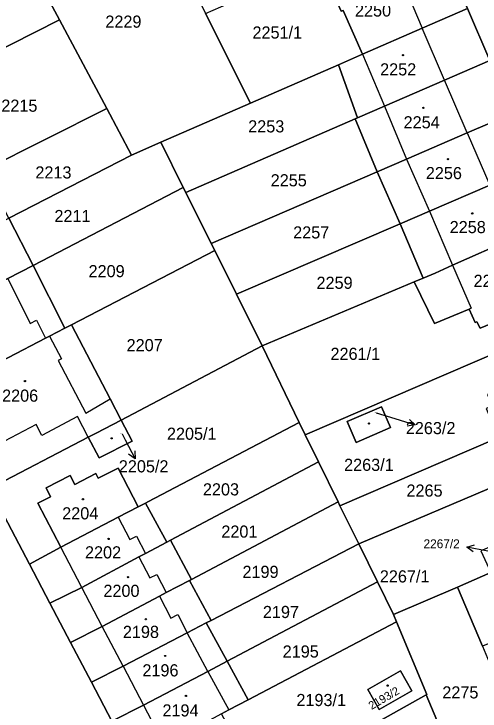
# Model space of a CAD drawing. Extents: x -596233 to -595156, y -1161235 to -1159375.
# Drawn here: x -595917.1 to -595851.8, y -1160689.1 to -1160591.4 of the extents above; entities that cross this region are included whole.
import ezdxf

# ---------------------------------------------------------------- set-up
doc = ezdxf.new("R2010")
doc.units = 0
for name, color, linetype in [('KN_CAR_KR', 7, 'Continuous'), ('KN_KULTURY', 7, 'Continuous'), ('KN_PARC_CIS_POM', 7, 'Continuous'), ('KN_PARC_CIS_POZ', 7, 'Continuous'), ('KN_PARC_CIS_STAV', 7, 'Continuous'), ('KN_PARC_PLOCHA', 7, 'Continuous'), ('PARC_C_SIPKA', 7, 'Continuous'), ('parcely_l', 7, 'Continuous')]:
    doc.layers.add(name, color=color, linetype=linetype)

msp = doc.modelspace()

# ---------------------------------------------------------------- linework, layer by layer
at = {"layer": 'KN_CAR_KR'}
for points in [[(-595863.31, -1160585.25), (-595859.91, -1160593.35)], [(-595856.78, -1160600.64), (-595859.91, -1160593.35)], [(-595868.26, -1160597), (-595865.21, -1160604.3)], [(-595853.61, -1160608.04), (-595856.78, -1160600.64)], [(-595865.21, -1160604.3), (-595862.1, -1160611.7)], [(-595853.61, -1160608.04), (-595850.46, -1160615.35)], [(-595862.1, -1160611.7), (-595858.89, -1160618.98)], [(-595858.89, -1160618.98), (-595855.67, -1160626.59)], [(-595855.67, -1160626.59), (-595853.07, -1160632.61)], [(-595917.95, -1160628.46), (-595914.82, -1160634.73)], [(-595853.07, -1160632.61), (-595853.34, -1160632.73)], [(-595914.82, -1160634.73), (-595913.93, -1160634.28)], [(-595913.93, -1160634.28), (-595912.67, -1160636.81)], [(-595912.11, -1160636.52), (-595910.45, -1160639.69)], [(-595910.45, -1160639.69), (-595910.92, -1160639.93)], [(-595910.92, -1160639.93), (-595907.05, -1160647.33)], [(-595907.05, -1160647.33), (-595903.64, -1160645.3)], [(-595908.21, -1160647.78), (-595913.17, -1160650.47)], [(-595906.69, -1160650.69), (-595908.21, -1160647.78)], [(-595913.99, -1160648.92), (-595918.41, -1160651.25)], [(-595913.17, -1160650.47), (-595913.99, -1160648.92)], [(-595902.5, -1160661.91), (-595900.86, -1160665.05)], [(-595900.86, -1160665.05), (-595899.93, -1160664.56)], [(-595899.93, -1160664.56), (-595898.66, -1160666.99)], [(-595907.6, -1160671.74), (-595910.53, -1160666.12)], [(-595899.59, -1160667.48), (-595898.05, -1160670.42)], [(-595898.05, -1160670.42), (-595897.09, -1160669.92)], [(-595897.09, -1160669.92), (-595895.76, -1160672.48)], [(-595904.73, -1160677.22), (-595907.6, -1160671.74)], [(-595896.71, -1160672.98), (-595895.13, -1160676.06)], [(-595895.13, -1160676.06), (-595894.13, -1160675.54)], [(-595894.13, -1160675.54), (-595892.81, -1160678.11)], [(-595901.82, -1160682.79), (-595904.73, -1160677.22)], [(-595889.96, -1160683.52), (-595892.81, -1160678.11)], [(-595901.82, -1160682.79), (-595898.96, -1160688.27)], [(-595889.96, -1160683.52), (-595887, -1160688.9)], [(-595898.96, -1160688.27), (-595896.07, -1160693.8)]]:
    msp.add_lwpolyline(points, dxfattribs=at)
at = {"layer": 'KN_KULTURY'}
for centre, radius in [((-595862.6, -1160597.13), 0.09), ((-595862.6, -1160597.13), 0.0398), ((-595859.75, -1160604.52), 0.09), ((-595859.75, -1160604.52), 0.0398), ((-595856.29, -1160611.71), 0.09), ((-595856.29, -1160611.71), 0.0398), ((-595852.9, -1160619.31), 0.09), ((-595852.9, -1160619.31), 0.0398), ((-595915.56, -1160642.82), 0.09), ((-595915.56, -1160642.82), 0.0398), ((-595867.35, -1160648.77), 0.09), ((-595867.35, -1160648.77), 0.0398), ((-595903.41, -1160650.85), 0.09), ((-595903.41, -1160650.85), 0.0398), ((-595907.43, -1160659.39), 0.09), ((-595907.43, -1160659.39), 0.0398), ((-595903.84, -1160664.95), 0.09), ((-595903.84, -1160664.95), 0.0398), ((-595901.13, -1160670.31), 0.09), ((-595901.13, -1160670.31), 0.0398), ((-595898.62, -1160676.21), 0.09), ((-595898.62, -1160676.21), 0.0398), ((-595895.91, -1160681.36), 0.09), ((-595895.91, -1160681.36), 0.0398), ((-595864.75, -1160685.51), 0.09), ((-595864.75, -1160685.51), 0.0398), ((-595893.01, -1160686.96), 0.09), ((-595893.01, -1160686.96), 0.0398)]:
    msp.add_circle(centre, radius, dxfattribs=at)
at = {"layer": 'KN_PARC_PLOCHA'}
for points in [[(-595850.43, -1160597.88), (-595853.57, -1160590.58), (-595859.06, -1160577.63), (-595864.83, -1160564.04), (-595868.29, -1160555.87), (-595870.71, -1160550.16), (-595874.62, -1160540.96), (-595876.97, -1160535.43), (-595882.36, -1160522.78), (-595882.91, -1160521.4), (-595885.64, -1160515.05), (-595887.02, -1160513.99), (-595888.53, -1160513.75), (-595890, -1160514.14), (-595887.17, -1160511.46), (-595869.41, -1160494.3), (-595869.87, -1160496.82), (-595869.71, -1160496.86), (-595864.99, -1160508.05), (-595863.86, -1160510.74), (-595864.05, -1160510.83), (-595853.97, -1160534.74), (-595853.68, -1160534.62), (-595849.94, -1160543.33)], [(-595955.55, -1160590.59), (-595949.46, -1160602.27), (-595945.4, -1160610.08), (-595938.93, -1160622.5), (-595935.44, -1160629.19), (-595932, -1160635.8), (-595927.43, -1160644.58), (-595920.5, -1160657.89), (-595914.93, -1160668.51), (-595912.07, -1160673.95), (-595909.16, -1160679.49), (-595906.25, -1160685.05), (-595903.39, -1160690.49)]]:
    msp.add_lwpolyline(points, dxfattribs=at)
for points in [[(-595907.77, -1160568.43), (-595898.29, -1160588.13), (-595892.95, -1160585.89), (-595890.25, -1160591.3), (-595883.98, -1160603.87), (-595896.51, -1160609.35), (-595900.63, -1160611.15), (-595904.1, -1160604.62), (-595910.73, -1160592.17), (-595914.88, -1160584.4), (-595916.4, -1160581.55), (-595909.61, -1160574.84), (-595910.51, -1160573.17), (-595910.44, -1160572.58), (-595910.47, -1160569.9), (-595912.95, -1160567.08), (-595910.04, -1160564.23), (-595909.12, -1160565.15)], [(-595853.57, -1160590.58), (-595859.91, -1160593.35), (-595868.26, -1160597), (-595870.96, -1160590.85), (-595871.24, -1160590.97), (-595872.13, -1160588.95), (-595871.85, -1160588.83), (-595872.24, -1160587.95), (-595873.19, -1160585.72), (-595869.74, -1160584.25), (-595868.71, -1160586.43), (-595868.32, -1160587.36), (-595863.31, -1160585.25), (-595864.76, -1160582.09), (-595869.74, -1160584.25), (-595870.47, -1160582.6), (-595859.06, -1160577.63)], [(-595869.74, -1160584.25), (-595873.19, -1160585.72), (-595872.24, -1160587.95), (-595871.85, -1160588.83), (-595872.13, -1160588.95), (-595871.24, -1160590.97), (-595870.96, -1160590.85), (-595868.26, -1160597), (-595871.65, -1160598.48), (-595883.98, -1160603.87), (-595890.25, -1160591.3), (-595878.46, -1160586.08), (-595870.47, -1160582.6)], [(-595910.73, -1160592.17), (-595927.71, -1160600.76), (-595931.73, -1160592.94), (-595928.1, -1160591.1), (-595921.51, -1160587.76), (-595914.88, -1160584.4)], [(-595850.43, -1160597.88), (-595856.78, -1160600.64), (-595865.21, -1160604.3), (-595868.97, -1160605.93), (-595871.65, -1160598.48), (-595868.26, -1160597), (-595859.91, -1160593.35), (-595853.57, -1160590.58)], [(-595904.1, -1160604.62), (-595921.23, -1160613.22), (-595927.71, -1160600.76), (-595910.73, -1160592.17)], [(-595847.25, -1160605.29), (-595853.61, -1160608.04), (-595862.1, -1160611.7), (-595866.23, -1160613.48), (-595869.29, -1160606.07), (-595868.97, -1160605.93), (-595865.21, -1160604.3), (-595856.78, -1160600.64), (-595850.43, -1160597.88)], [(-595868.97, -1160605.93), (-595869.29, -1160606.07), (-595893.02, -1160616.38), (-595893.38, -1160615.67), (-595896.51, -1160609.35), (-595883.98, -1160603.87), (-595871.65, -1160598.48)], [(-595900.63, -1160611.15), (-595917.79, -1160619.98), (-595921.37, -1160613.3), (-595921.23, -1160613.22), (-595904.1, -1160604.62)], [(-595844.08, -1160612.6), (-595850.46, -1160615.35), (-595858.89, -1160618.98), (-595863.02, -1160620.76), (-595866.23, -1160613.48), (-595862.1, -1160611.7), (-595853.61, -1160608.04), (-595847.25, -1160605.29)], [(-595866.23, -1160613.48), (-595889.47, -1160623.52), (-595893.02, -1160616.38), (-595869.29, -1160606.07)], [(-595893.38, -1160615.67), (-595914.4, -1160626.61), (-595917.79, -1160619.98), (-595900.63, -1160611.15), (-595896.51, -1160609.35)], [(-595840.89, -1160620), (-595847.24, -1160622.83), (-595855.67, -1160626.59), (-595858.09, -1160627.67), (-595859.78, -1160628.38), (-595863.02, -1160620.76), (-595858.89, -1160618.98), (-595850.46, -1160615.35), (-595844.08, -1160612.6)], [(-595863.02, -1160620.76), (-595885.93, -1160630.64), (-595888.98, -1160624.5), (-595889.47, -1160623.52), (-595866.23, -1160613.48)], [(-595893.02, -1160616.38), (-595889.47, -1160623.52), (-595888.98, -1160624.5), (-595909.03, -1160634.92), (-595909.97, -1160635.41), (-595914.4, -1160626.61), (-595893.38, -1160615.67)], [(-595914.4, -1160626.61), (-595917.95, -1160628.46), (-595927.63, -1160633.5), (-595932, -1160635.8), (-595935.44, -1160629.19), (-595931.11, -1160626.83), (-595921.44, -1160621.85), (-595917.79, -1160619.98)], [(-595835.36, -1160632.84), (-595844.53, -1160636.68), (-595876.32, -1160650.35), (-595877.14, -1160648.64), (-595882.32, -1160637.89), (-595861.05, -1160628.92), (-595858.18, -1160634.77), (-595853.34, -1160632.73), (-595852.51, -1160634.63), (-595852.24, -1160634.5), (-595851.81, -1160635.41), (-595848.3, -1160633.96), (-595847.54, -1160635.72), (-595842.31, -1160633.44), (-595843.49, -1160630.75), (-595843.76, -1160630.87), (-595847.24, -1160622.83), (-595840.89, -1160620)], [(-595859.78, -1160628.38), (-595861.05, -1160628.92), (-595882.32, -1160637.89), (-595885.93, -1160630.64), (-595863.02, -1160620.76)], [(-595843.76, -1160630.87), (-595848.71, -1160633.03), (-595848.3, -1160633.96), (-595851.81, -1160635.41), (-595852.24, -1160634.5), (-595852.51, -1160634.63), (-595853.34, -1160632.73), (-595858.18, -1160634.77), (-595861.05, -1160628.92), (-595859.78, -1160628.38), (-595858.09, -1160627.67), (-595855.67, -1160626.59), (-595847.24, -1160622.83)], [(-595885.93, -1160630.64), (-595882.32, -1160637.89), (-595902.08, -1160648.28), (-595903.64, -1160645.3), (-595909.03, -1160634.92), (-595888.98, -1160624.5)], [(-595909.97, -1160635.41), (-595912.11, -1160636.52), (-595912.67, -1160636.81), (-595923.09, -1160642.23), (-595927.43, -1160644.58), (-595932, -1160635.8), (-595927.63, -1160633.5), (-595917.95, -1160628.46), (-595914.4, -1160626.61)], [(-595831, -1160642.97), (-595837.31, -1160645.64), (-595839.77, -1160640.06), (-595840.3, -1160638.84), (-595840.87, -1160637.55), (-595842.39, -1160638.23), (-595841.83, -1160639.51), (-595847.32, -1160641.83), (-595846.82, -1160643.05), (-595850.77, -1160644.68), (-595850.1, -1160646.33), (-595850.94, -1160646.67), (-595850.45, -1160647.88), (-595849.62, -1160647.54), (-595849.05, -1160648.95), (-595846.89, -1160648.09), (-595846.32, -1160649.51), (-595849.65, -1160650.94), (-595871.43, -1160660.3), (-595871.7, -1160659.76), (-595874.46, -1160654.13), (-595876.32, -1160650.35), (-595844.53, -1160636.68), (-595835.36, -1160632.84)], [(-595902.08, -1160648.28), (-595905.59, -1160650.12), (-595906.69, -1160650.69), (-595920.5, -1160657.89), (-595927.43, -1160644.58), (-595923.09, -1160642.23), (-595912.67, -1160636.81), (-595912.11, -1160636.52), (-595909.97, -1160635.41), (-595909.03, -1160634.92), (-595903.64, -1160645.3)], [(-595877.14, -1160648.64), (-595898.34, -1160659.73), (-595898.69, -1160659.92), (-595899.69, -1160660.44), (-595902.51, -1160655.03), (-595905.28, -1160656.43), (-595905.61, -1160655.78), (-595908.58, -1160657.3), (-595909.22, -1160656.05), (-595912.6, -1160657.79), (-595911.96, -1160659.03), (-595913.76, -1160659.94), (-595910.53, -1160666.12), (-595914.93, -1160668.51), (-595920.5, -1160657.89), (-595906.69, -1160650.69), (-595905.17, -1160653.6), (-595900.53, -1160651.24), (-595902.08, -1160648.28), (-595882.32, -1160637.89)], [(-595864.35, -1160649.33), (-595865.6, -1160646.42), (-595870.42, -1160648.49), (-595869.17, -1160651.41)], [(-595864.35, -1160649.33), (-595869.17, -1160651.41), (-595870.42, -1160648.49), (-595865.6, -1160646.42)], [(-595906.69, -1160650.69), (-595905.59, -1160650.12), (-595902.08, -1160648.28), (-595900.53, -1160651.24), (-595905.17, -1160653.6)], [(-595876.32, -1160650.35), (-595874.46, -1160654.13), (-595895.17, -1160665.14), (-595895.7, -1160665.42), (-595898.69, -1160659.92), (-595898.34, -1160659.73), (-595877.14, -1160648.64)], [(-595824.38, -1160658.64), (-595845.74, -1160667.72), (-595847.02, -1160664.67), (-595851.7, -1160666.61), (-595850.29, -1160669.65), (-595854.95, -1160671.69), (-595863.95, -1160675.53), (-595866.19, -1160670.97), (-595868.8, -1160665.65), (-595847.45, -1160656.58), (-595845.51, -1160661.27), (-595842.64, -1160660.04), (-595841.88, -1160661.84), (-595841.41, -1160662.94), (-595838.21, -1160661.58), (-595838.06, -1160661.96), (-595835, -1160660.72), (-595835.61, -1160659.21), (-595832.22, -1160657.78), (-595833.3, -1160654.81), (-595833.44, -1160654.87), (-595834.95, -1160651.27), (-595828.66, -1160648.5)], [(-595847.45, -1160656.58), (-595868.8, -1160665.65), (-595871.43, -1160660.3), (-595849.65, -1160650.94)], [(-595871.7, -1160659.76), (-595892.24, -1160670.62), (-595895.17, -1160665.14), (-595874.46, -1160654.13)], [(-595899.69, -1160660.44), (-595902.5, -1160661.91), (-595910.53, -1160666.12), (-595913.76, -1160659.94), (-595911.96, -1160659.03), (-595912.6, -1160657.79), (-595909.22, -1160656.05), (-595908.58, -1160657.3), (-595905.61, -1160655.78), (-595905.28, -1160656.43), (-595902.51, -1160655.03)], [(-595815.5, -1160679.63), (-595824.33, -1160683.37), (-595824.27, -1160683.51), (-595827.83, -1160685.01), (-595827.89, -1160684.87), (-595829.92, -1160685.73), (-595830.37, -1160686.99), (-595844.66, -1160677.14), (-595848.07, -1160678.57), (-595851.48, -1160679.99), (-595854.95, -1160671.69), (-595850.29, -1160669.65), (-595845.74, -1160667.72), (-595824.38, -1160658.64)], [(-595895.7, -1160665.42), (-595898.66, -1160666.99), (-595899.59, -1160667.48), (-595907.6, -1160671.74), (-595912.07, -1160673.95), (-595914.93, -1160668.51), (-595910.53, -1160666.12), (-595902.5, -1160661.91), (-595899.69, -1160660.44), (-595898.69, -1160659.92)], [(-595871.43, -1160660.3), (-595868.8, -1160665.65), (-595889.48, -1160676.38), (-595892.52, -1160670.77), (-595892.24, -1160670.62), (-595871.7, -1160659.76)], [(-595892.24, -1160670.62), (-595892.52, -1160670.77), (-595895.76, -1160672.48), (-595896.71, -1160672.98), (-595904.73, -1160677.22), (-595909.16, -1160679.49), (-595912.07, -1160673.95), (-595907.6, -1160671.74), (-595899.59, -1160667.48), (-595898.66, -1160666.99), (-595895.7, -1160665.42), (-595895.17, -1160665.14)], [(-595866.19, -1160670.97), (-595887.25, -1160682.09), (-595890.15, -1160676.73), (-595889.48, -1160676.38), (-595868.8, -1160665.65)], [(-595889.48, -1160676.38), (-595890.15, -1160676.73), (-595892.81, -1160678.11), (-595901.82, -1160682.79), (-595906.25, -1160685.05), (-595909.16, -1160679.49), (-595904.73, -1160677.22), (-595896.71, -1160672.98), (-595895.76, -1160672.48), (-595892.52, -1160670.77)], [(-595863.95, -1160675.53), (-595863.51, -1160676.59), (-595884.3, -1160687.49), (-595887.25, -1160682.09), (-595866.19, -1160670.97)], [(-595851.48, -1160679.99), (-595845.86, -1160693.46), (-595845.23, -1160694.98), (-595854.38, -1160698.69), (-595859.36, -1160686.81), (-595859.25, -1160686.75), (-595863.51, -1160676.59), (-595863.95, -1160675.53), (-595854.95, -1160671.69)], [(-595887.25, -1160682.09), (-595889.96, -1160683.52), (-595898.96, -1160688.27), (-595903.39, -1160690.49), (-595906.25, -1160685.05), (-595901.82, -1160682.79), (-595892.81, -1160678.11), (-595890.15, -1160676.73)], [(-595859.36, -1160686.81), (-595867.78, -1160691.53), (-595875.71, -1160695.98), (-595894.87, -1160706.72), (-595900.49, -1160696.02), (-595896.07, -1160693.8), (-595892.83, -1160700.01), (-595891.03, -1160699.03), (-595890.39, -1160700.27), (-595889.3, -1160699.7), (-595887.01, -1160698.46), (-595887.68, -1160697.22), (-595884.73, -1160695.63), (-595888.01, -1160689.45), (-595887, -1160688.9), (-595884.3, -1160687.49), (-595863.51, -1160676.59), (-595859.25, -1160686.75)], [(-595884.3, -1160687.49), (-595887, -1160688.9), (-595888.01, -1160689.45), (-595896.07, -1160693.8), (-595900.49, -1160696.02), (-595903.39, -1160690.49), (-595898.96, -1160688.27), (-595889.96, -1160683.52), (-595887.25, -1160682.09)], [(-595861.36, -1160686.24), (-595862.94, -1160683.46), (-595867.53, -1160686.07), (-595865.95, -1160688.85)], [(-595861.36, -1160686.24), (-595865.95, -1160688.85), (-595867.53, -1160686.07), (-595862.94, -1160683.46)], [(-595854.38, -1160698.69), (-595863.27, -1160702.25), (-595863.62, -1160701.42), (-595867.78, -1160691.53), (-595859.36, -1160686.81)]]:
    msp.add_lwpolyline(points, close=True, dxfattribs=at)
at = {"layer": 'PARC_C_SIPKA'}
for points in [[(-595866.34, -1160647.26), (-595863.76, -1160648.07), (-595860.8966, -1160648.9648)], [(-595861.7019, -1160648.1893), (-595860.8966, -1160648.9648), (-595862.0002, -1160649.1438)], [(-595901.95, -1160650.23), (-595901.52, -1160651.05), (-595900.1357, -1160653.7115)], [(-595900.1535, -1160652.5936), (-595900.1357, -1160653.7115), (-595901.0407, -1160653.0551)], [(-595852.7587, -1160666.7692), (-595853.6449, -1160666.0876), (-595852.5679, -1160665.7876)], [(-595848.55, -1160667.08), (-595850.7, -1160666.66), (-595853.6449, -1160666.0876)]]:
    msp.add_lwpolyline(points, dxfattribs=at)
at = {"layer": 'parcely_l'}
for points in [[(-595868.26, -1160597), (-595870.96, -1160590.85), (-595871.24, -1160590.97), (-595872.13, -1160588.95), (-595871.85, -1160588.83), (-595872.24, -1160587.95), (-595873.19, -1160585.72), (-595869.74, -1160584.25)], [(-595910.73, -1160592.17), (-595914.88, -1160584.4)], [(-595853.57, -1160590.58), (-595859.91, -1160593.35), (-595868.26, -1160597)], [(-595850.43, -1160597.88), (-595853.57, -1160590.58)], [(-595910.73, -1160592.17), (-595927.71, -1160600.76)], [(-595904.1, -1160604.62), (-595910.73, -1160592.17)], [(-595890.25, -1160591.3), (-595883.98, -1160603.87)], [(-595871.65, -1160598.48), (-595868.26, -1160597)], [(-595850.43, -1160597.88), (-595856.78, -1160600.64), (-595865.21, -1160604.3), (-595868.97, -1160605.93)], [(-595883.98, -1160603.87), (-595871.65, -1160598.48)], [(-595871.65, -1160598.48), (-595868.97, -1160605.93)], [(-595883.98, -1160603.87), (-595896.51, -1160609.35)], [(-595904.1, -1160604.62), (-595921.23, -1160613.22)], [(-595900.63, -1160611.15), (-595904.1, -1160604.62)], [(-595847.25, -1160605.29), (-595853.61, -1160608.04), (-595862.1, -1160611.7), (-595866.23, -1160613.48)], [(-595893.02, -1160616.38), (-595869.29, -1160606.07)], [(-595868.97, -1160605.93), (-595869.29, -1160606.07)], [(-595869.29, -1160606.07), (-595866.23, -1160613.48)], [(-595896.51, -1160609.35), (-595900.63, -1160611.15)], [(-595896.51, -1160609.35), (-595893.38, -1160615.67)], [(-595917.79, -1160619.98), (-595900.63, -1160611.15)], [(-595844.08, -1160612.6), (-595850.46, -1160615.35), (-595858.89, -1160618.98), (-595863.02, -1160620.76)], [(-595866.23, -1160613.48), (-595889.47, -1160623.52)], [(-595866.23, -1160613.48), (-595863.02, -1160620.76)], [(-595893.38, -1160615.67), (-595914.4, -1160626.61)], [(-595893.38, -1160615.67), (-595893.02, -1160616.38)], [(-595889.47, -1160623.52), (-595893.02, -1160616.38)], [(-595914.4, -1160626.61), (-595917.79, -1160619.98)], [(-595885.93, -1160630.64), (-595863.02, -1160620.76)], [(-595863.02, -1160620.76), (-595859.78, -1160628.38)], [(-595859.78, -1160628.38), (-595858.09, -1160627.67), (-595855.67, -1160626.59), (-595847.24, -1160622.83)], [(-595888.98, -1160624.5), (-595889.47, -1160623.52)], [(-595888.98, -1160624.5), (-595909.03, -1160634.92)], [(-595885.93, -1160630.64), (-595888.98, -1160624.5)], [(-595932, -1160635.8), (-595927.63, -1160633.5), (-595917.95, -1160628.46), (-595914.4, -1160626.61)], [(-595914.4, -1160626.61), (-595909.97, -1160635.41)], [(-595861.05, -1160628.92), (-595882.32, -1160637.89)], [(-595859.78, -1160628.38), (-595861.05, -1160628.92)], [(-595861.05, -1160628.92), (-595858.18, -1160634.77), (-595853.34, -1160632.73), (-595852.51, -1160634.63), (-595852.24, -1160634.5), (-595851.81, -1160635.41), (-595848.3, -1160633.96)], [(-595882.32, -1160637.89), (-595885.93, -1160630.64)], [(-595835.36, -1160632.84), (-595844.53, -1160636.68), (-595876.32, -1160650.35)], [(-595909.03, -1160634.92), (-595909.97, -1160635.41)], [(-595902.08, -1160648.28), (-595903.64, -1160645.3), (-595909.03, -1160634.92)], [(-595909.97, -1160635.41), (-595912.11, -1160636.52), (-595912.67, -1160636.81), (-595923.09, -1160642.23), (-595927.43, -1160644.58)], [(-595902.08, -1160648.28), (-595882.32, -1160637.89)], [(-595882.32, -1160637.89), (-595877.14, -1160648.64)], [(-595864.35, -1160649.33), (-595869.17, -1160651.41), (-595870.42, -1160648.49), (-595865.6, -1160646.42), (-595864.35, -1160649.33)], [(-595906.69, -1160650.69), (-595905.17, -1160653.6), (-595900.53, -1160651.24), (-595902.08, -1160648.28)], [(-595906.69, -1160650.69), (-595905.59, -1160650.12), (-595902.08, -1160648.28)], [(-595877.14, -1160648.64), (-595898.34, -1160659.73), (-595898.69, -1160659.92)], [(-595876.32, -1160650.35), (-595877.14, -1160648.64)], [(-595920.5, -1160657.89), (-595906.69, -1160650.69)], [(-595874.46, -1160654.13), (-595876.32, -1160650.35)], [(-595871.43, -1160660.3), (-595849.65, -1160650.94)], [(-595895.17, -1160665.14), (-595874.46, -1160654.13)], [(-595874.46, -1160654.13), (-595871.7, -1160659.76)], [(-595910.53, -1160666.12), (-595913.76, -1160659.94), (-595911.96, -1160659.03), (-595912.6, -1160657.79), (-595909.22, -1160656.05), (-595908.58, -1160657.3), (-595905.61, -1160655.78), (-595905.28, -1160656.43), (-595902.51, -1160655.03), (-595899.69, -1160660.44)], [(-595868.8, -1160665.65), (-595847.45, -1160656.58)], [(-595920.5, -1160657.89), (-595914.93, -1160668.51)], [(-595899.69, -1160660.44), (-595902.5, -1160661.91), (-595910.53, -1160666.12)], [(-595899.69, -1160660.44), (-595898.69, -1160659.92)], [(-595898.69, -1160659.92), (-595895.7, -1160665.42)], [(-595871.7, -1160659.76), (-595892.24, -1160670.62)], [(-595871.7, -1160659.76), (-595871.43, -1160660.3)], [(-595868.8, -1160665.65), (-595871.43, -1160660.3)], [(-595895.7, -1160665.42), (-595898.66, -1160666.99), (-595899.59, -1160667.48), (-595907.6, -1160671.74), (-595912.07, -1160673.95)], [(-595895.7, -1160665.42), (-595895.17, -1160665.14)], [(-595892.24, -1160670.62), (-595895.17, -1160665.14)], [(-595914.93, -1160668.51), (-595910.53, -1160666.12)], [(-595889.48, -1160676.38), (-595868.8, -1160665.65)], [(-595868.8, -1160665.65), (-595866.19, -1160670.97)], [(-595914.93, -1160668.51), (-595912.07, -1160673.95)], [(-595854.95, -1160671.69), (-595850.29, -1160669.65)], [(-595892.52, -1160670.77), (-595895.76, -1160672.48), (-595896.71, -1160672.98), (-595904.73, -1160677.22), (-595909.16, -1160679.49)], [(-595892.24, -1160670.62), (-595892.52, -1160670.77)], [(-595892.52, -1160670.77), (-595889.48, -1160676.38)], [(-595866.19, -1160670.97), (-595887.25, -1160682.09)], [(-595866.19, -1160670.97), (-595863.95, -1160675.53)], [(-595863.95, -1160675.53), (-595854.95, -1160671.69)], [(-595851.48, -1160679.99), (-595854.95, -1160671.69)], [(-595912.07, -1160673.95), (-595909.16, -1160679.49)], [(-595863.95, -1160675.53), (-595863.51, -1160676.59)], [(-595906.25, -1160685.05), (-595901.82, -1160682.79), (-595892.81, -1160678.11), (-595890.15, -1160676.73)], [(-595890.15, -1160676.73), (-595889.48, -1160676.38)], [(-595887.25, -1160682.09), (-595890.15, -1160676.73)], [(-595863.51, -1160676.59), (-595884.3, -1160687.49)], [(-595859.36, -1160686.81), (-595859.25, -1160686.75), (-595863.51, -1160676.59)], [(-595909.16, -1160679.49), (-595906.25, -1160685.05)], [(-595903.39, -1160690.49), (-595898.96, -1160688.27), (-595889.96, -1160683.52), (-595887.25, -1160682.09)], [(-595884.3, -1160687.49), (-595887.25, -1160682.09)], [(-595861.36, -1160686.24), (-595865.95, -1160688.85), (-595867.53, -1160686.07), (-595862.94, -1160683.46), (-595861.36, -1160686.24)], [(-595906.25, -1160685.05), (-595903.39, -1160690.49)], [(-595867.78, -1160691.53), (-595859.36, -1160686.81)], [(-595854.38, -1160698.69), (-595859.36, -1160686.81)], [(-595884.3, -1160687.49), (-595887, -1160688.9), (-595888.01, -1160689.45)]]:
    msp.add_lwpolyline(points, dxfattribs=at)

# ---------------------------------------------------------------- texts
at = {"layer": 'KN_PARC_CIS_POM'}
for s, p in [('2263/2', (-595866.6233, -1160647.26)), ('2205/2', (-595902.2333, -1160650.23))]:
    msp.add_text(s, height=0.1, dxfattribs=at).set_placement(p)
at = {"layer": 'KN_PARC_CIS_POZ'}
for s, p in [('2229', (-595904.2966, -1160593.28)), ('2251/1', (-595883.6866, -1160594.8)), ('2215', (-595918.8666, -1160605.06)), ('2253', (-595884.2866, -1160607.96)), ('2213', (-595914.0966, -1160614.42)), ('2255', (-595881.1366, -1160615.52)), ('2211', (-595911.4266, -1160620.53)), ('2257', (-595877.9866, -1160622.83)), ('2209', (-595906.6466, -1160628.26)), ('2259', (-595874.7166, -1160629.89)), ('2207', (-595901.3166, -1160638.63)), ('2261/1', (-595872.7566, -1160639.85)), ('2205/1', (-595895.6666, -1160651.05)), ('2263/1', (-595870.8566, -1160655.41)), ('2203', (-595890.6266, -1160658.85)), ('2265', (-595862.1166, -1160659.02)), ('2201', (-595888.0466, -1160664.77)), ('2199', (-595885.0866, -1160670.41)), ('2267/1', (-595865.8466, -1160671.05)), ('2197', (-595882.2266, -1160676.04)), ('2195', (-595879.4566, -1160681.58)), ('2275', (-595857.0966, -1160687.31)), ('2193/1', (-595877.5366, -1160688.38))]:
    msp.add_text(s, height=1.7, dxfattribs=at).set_placement(p)
at = {"layer": 'KN_PARC_CIS_STAV'}
for s, height, p in [('2250', 1.7, (-595869.3266, -1160591.72)), ('2252', 1.7, (-595865.8066, -1160599.97)), ('2254', 1.7, (-595862.5166, -1160607.39)), ('2256', 1.7, (-595859.4066, -1160614.51)), ('2258', 1.7, (-595856.0666, -1160622.08)), ('2260', 1.7, (-595852.7166, -1160629.62)), ('2206', 1.7, (-595918.7566, -1160645.71)), ('2263/2', 1.7, (-595862.2066, -1160650.26)), ('2205/2', 1.7, (-595902.4066, -1160655.62)), ('2204', 1.7, (-595910.3366, -1160662.21)), ('2267/2', 1.24, (-595859.7233, -1160666.246)), ('2202', 1.7, (-595907.1466, -1160667.68)), ('2200', 1.7, (-595904.5666, -1160673.07)), ('2198', 1.7, (-595901.8366, -1160678.83)), ('2196', 1.7, (-595899.1066, -1160684.22)), ('2194', 1.7, (-595896.2966, -1160689.84))]:
    msp.add_text(s, height=height, dxfattribs=at).set_placement(p)
msp.add_text('2193/2', height=1.14, rotation=30.440426, dxfattribs=at).set_placement((-595867.0047, -1160688.9357))

doc.saveas('drawing.dxf')
